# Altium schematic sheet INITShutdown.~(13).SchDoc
size A4
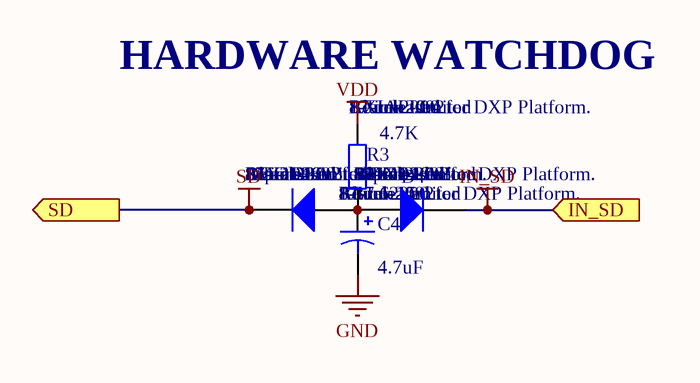
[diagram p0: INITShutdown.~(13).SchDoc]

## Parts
C4  value 4.7uF  Published: 8-Jun-2000  LatestRevisionDate: 17-Jul-2002  LatestRevisionNote: Re-released for DXP Platform.  PackageReference: RB7.6-15  Publisher: Altium Limited  [CAPPR2.5-6.3X5]  (hidden comment: Cap Pol1)
D3  Published: 8-Jun-2000  LatestRevisionDate: 17-Jul-2002  LatestRevisionNote: Re-released for DXP Platform.  PackageDocument: Sep-1996  PackageReference: SMC  Publisher: Altium Limited  Code_JEDEC: DO-214-AB  [DO-204AL]  (hidden comment: Diode)
D4  Published: 8-Jun-2000  LatestRevisionDate: 17-Jul-2002  LatestRevisionNote: Re-released for DXP Platform.  PackageDocument: Sep-1996  PackageReference: SMC  Publisher: Altium Limited  Code_JEDEC: DO-214-AB  [DO-204AL]  (hidden comment: Diode)
R3  value 4.7K  Published: 8-Jun-2000  LatestRevisionDate: 17-Jul-2002  LatestRevisionNote: Re-released for DXP Platform.  PackageReference: AXIAL-0.4  Publisher: Altium Limited  [AXIAL-0.3]  (hidden comment: Res2)

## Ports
IN_SD (in), SD (out)

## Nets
GND: C4.2
IN_SD: D4.2(K) ; port IN_SD
SD: D3.2(K) ; port SD
VDD: R3.2
NetC4_1: C4.1 D3.1(A) D4.1(A) R3.1

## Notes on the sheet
- (near R3) HARDWARE WATCHDOG

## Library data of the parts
C4 = Cap Pol1: Polarized Capacitor (Radial)
D3 D4 = Diode: 1n4148
R3 = Res2: Resistor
